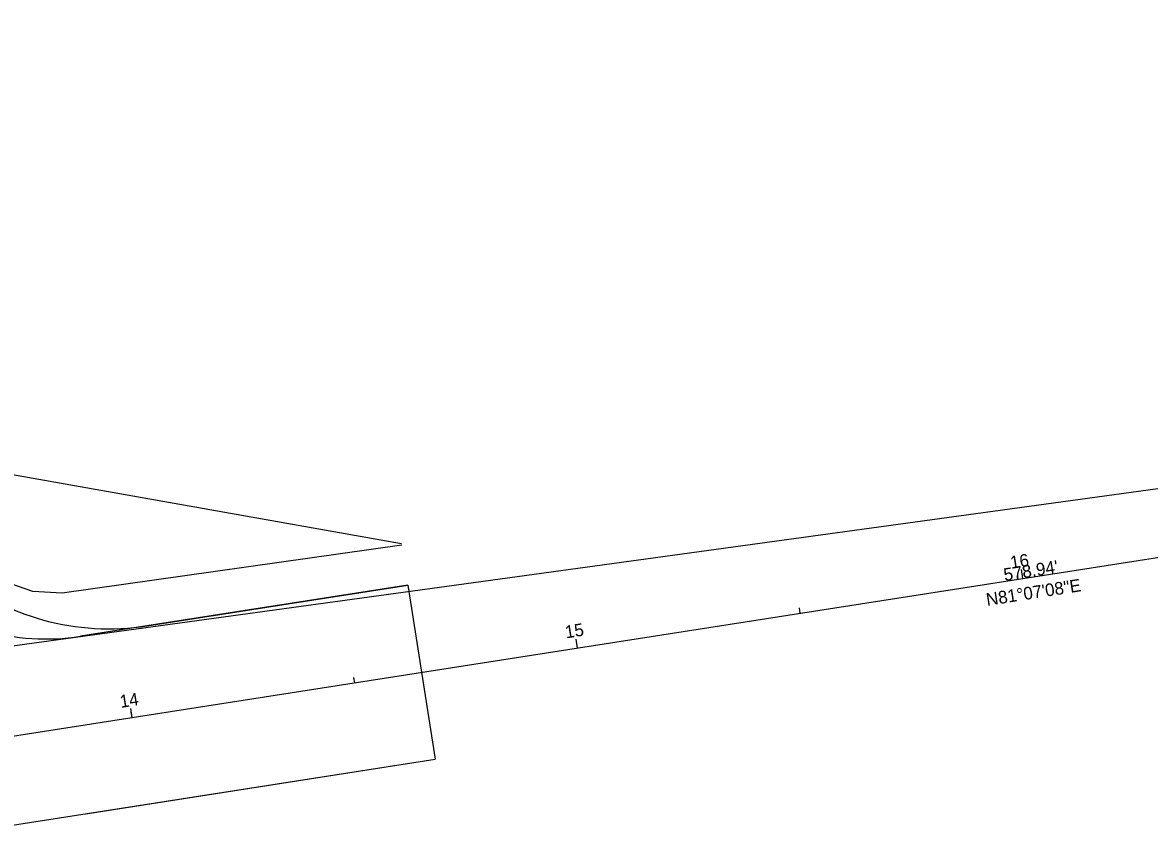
# Model space of a CAD drawing. Extents: x 219353 to 221640, y 361458 to 364236.
# Drawn here: x 220633.9 to 220883.9, y 362149.8 to 362328.9 of the extents above; entities that cross this region are included whole.
import ezdxf

# ---------------------------------------------------------------- set-up
doc = ezdxf.new("R2010")
doc.units = 0
for name, color, linetype in [('Default', 7, 'Continuous'), ('DR_P_Cells', 7, 'Continuous'), ('DR_P_GenericNode', 7, 'Continuous'), ('DR_X_GenericNode', 7, 'Continuous'), ('DT_X_Contour_Major', 7, 'Continuous'), ('DT_X_Contour_Minor', 7, 'Continuous'), ('SC_ProfileRun1', 7, 'Continuous'), ('SC_ProfileRun3', 7, 'Continuous'), ('SC_Scratch1', 7, 'Continuous'), ('UT_X_San_Storm_Line', 7, 'Continuous'), ('UT_X_Sanitary_Cells', 7, 'Continuous'), ('UT_X_Sanitary_Line', 7, 'Continuous')]:
    doc.layers.add(name, color=color, linetype=linetype)

msp = doc.modelspace()

# ---------------------------------------------------------------- linework, layer by layer
at = {"layer": 'Default'}
msp.add_line((220718.01, 362213.16), (220611.49, 362232.06), dxfattribs=at)
at = {"layer": 'DR_X_GenericNode'}
for p, q in [((220718.04, 362212.92), (220642.7, 362202.21)), ((220636.18, 362202.62), (220625.13, 362206.46)), ((220719.43, 362204.03), (220646.78, 362192.68)), ((220642.7, 362202.21), (220636.18, 362202.62)), ((220625.65, 362149.8), (220725.47, 362165.4))]:
    msp.add_line(p, q, dxfattribs=at)
msp.add_arc((220639.06, 362242.08), 50, 179.8811, 278.8811, dxfattribs=at)
at = {"layer": 'DT_X_Contour_Major'}
msp.add_line((220572.38, 362161.22), (221144.38, 362250.6), dxfattribs=at)
msp.add_line((220572.38, 362161.22), (221144.38, 362250.6), dxfattribs=at)
at = {"layer": 'DT_X_Contour_Minor'}
for p, q in [((220482.39, 362170.13), (221640, 362328.87)), ((220661.54, 362194.98), (220719.43, 362204.03)), ((220719.43, 362204.03), (220661.54, 362194.98)), ((220705.6, 362201.87), (220719.43, 362204.03)), ((220625.65, 362149.8), (220725.47, 362165.4)), ((220625.65, 362149.8), (220725.47, 362165.4)), ((220647.94, 362153.29), (220725.47, 362165.4))]:
    msp.add_line(p, q, dxfattribs=at)
msp.add_arc((220653.05, 362249.33), 55, 182.2506, 278.8811, dxfattribs=at)
msp.add_arc((220653.05, 362249.33), 55, 182.2506, 278.8811, dxfattribs=at)
at = {"layer": 'SC_ProfileRun3'}
for p, q in [((220855.84, 362205.51), (220855.66, 362206.69)), ((220757.04, 362190.07), (220756.73, 362192.05)), ((220658.24, 362174.63), (220658.05, 362175.82))]:
    msp.add_line(p, q, dxfattribs=at)
at = {"layer": 'UT_X_San_Storm_Line'}
for p, q in [((220661.54, 362194.98), (220719.43, 362204.03)), ((220625.65, 362149.8), (220725.47, 362165.4))]:
    msp.add_line(p, q, dxfattribs=at)
msp.add_arc((220653.05, 362249.33), 55, 182.2506, 278.8811, dxfattribs=at)
at = {"layer": 'UT_X_Sanitary_Cells'}
for p, q in [((220855.84, 362205.51), (220855.53, 362207.48)), ((220806.44, 362197.79), (220806.25, 362198.97)), ((220757.04, 362190.07), (220756.73, 362192.05)), ((220707.64, 362182.35), (220707.45, 362183.54)), ((220658.24, 362174.63), (220657.93, 362176.61))]:
    msp.add_line(p, q, dxfattribs=at)
at = {"layer": 'UT_X_Sanitary_Line'}
msp.add_line((220719.43, 362204.03), (220725.47, 362165.4), dxfattribs=at)

# ---------------------------------------------------------------- texts
at = {"layer": 'DR_P_Cells'}
msp.add_text("578.94'", height=2.8, rotation=8.8811, dxfattribs=at).set_placement((220851.78, 362204.92))
at = {"layer": 'DR_P_GenericNode'}
msp.add_text("578.94'", height=2.8, rotation=8.8811, dxfattribs=at).set_placement((220851.78, 362204.92))
at = {"layer": 'SC_ProfileRun1'}
msp.add_text('N81°07\'08"E', height=2.8, rotation=8.8811, dxfattribs=at).set_placement((220847.9, 362199.41))
at = {"layer": 'SC_ProfileRun3'}
msp.add_text('15', height=2.8, rotation=8.8811, dxfattribs=at).set_placement((220754.49, 362192.2))
at = {"layer": 'SC_Scratch1'}
msp.add_text('N81°07\'08"E', height=2.8, rotation=8.8811, dxfattribs=at).set_placement((220847.9, 362199.41))
at = {"layer": 'UT_X_Sanitary_Cells'}
for s, p in [('16', (220853.24, 362207.63)), ('15', (220754.49, 362192.2)), ('14', (220655.72, 362176.77))]:
    msp.add_text(s, height=2.8, rotation=8.8811, dxfattribs=at).set_placement(p)

doc.saveas('drawing.dxf')
